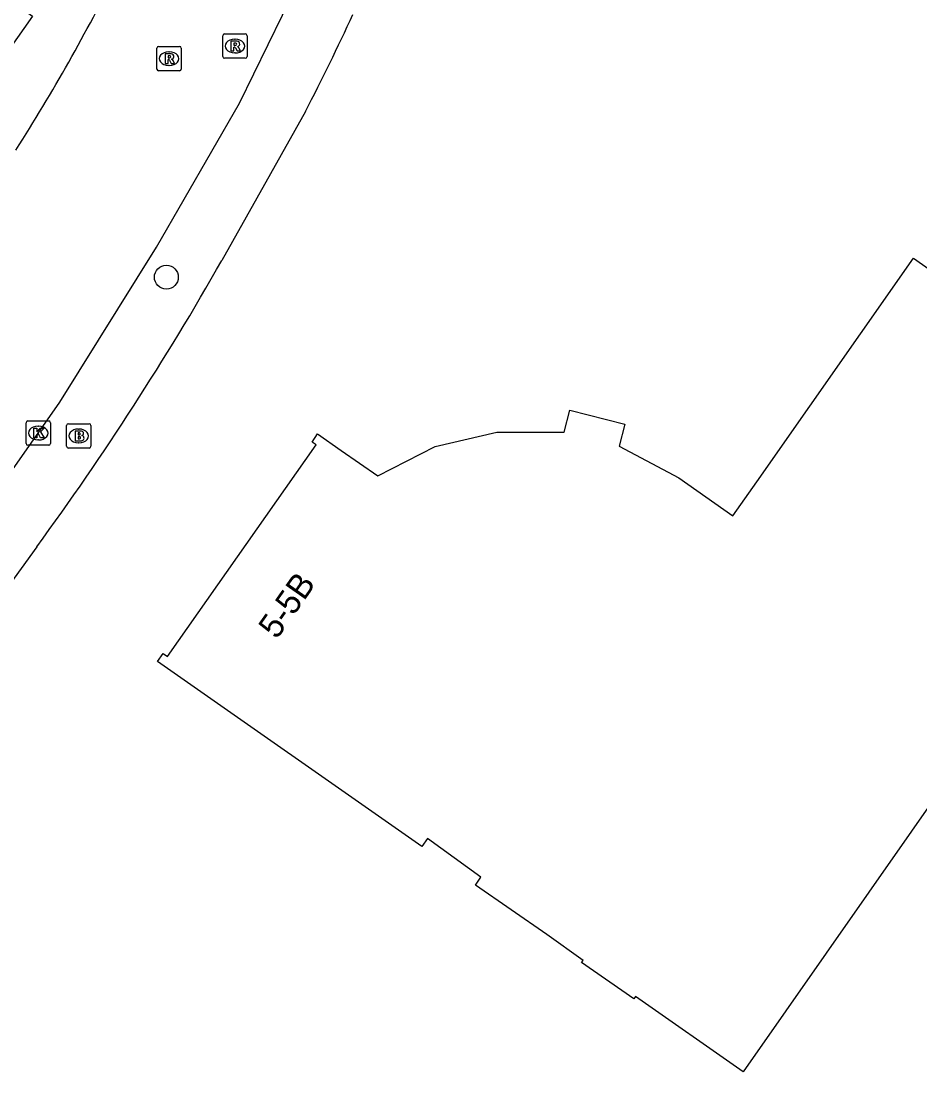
# Model space of a CAD drawing. Extents: x 155018 to 156648, y 383980 to 385733.
# Drawn here: x 155508.09 to 155544.91, y 385089.36 to 385132.44 of the extents above; entities that cross this region are included whole.
import ezdxf

# ---------------------------------------------------------------- set-up
doc = ezdxf.new("R2010")
doc.units = 0
for name, color, linetype in [('IMGEO_Boom', 7, 'Continuous'), ('IMGEO_Brandkraan', 7, 'Continuous'), ('IMGEO_Kolk', 7, 'Continuous'), ('IMGEO_Pand', 7, 'Continuous'), ('IMGEO_Pand_nummerreeks', 7, 'Continuous'), ('IMGEO_Rijbaan_lokaal_gesloten', 7, 'Continuous'), ('IMGEO_Rioolput', 7, 'Continuous'), ('IMGEO_Voetpad_open', 7, 'Continuous')]:
    doc.layers.add(name, color=color, linetype=linetype)

msp = doc.modelspace()

# ---------------------------------------------------------------- linework, layer by layer
at = {"layer": 'IMGEO_Boom'}
msp.add_circle((155514.041, 385121.939), 0.489, dxfattribs=at)
at = {"layer": 'IMGEO_Brandkraan'}
for p, q in [((155510.026, 385115.934), (155510.878, 385115.934)), ((155509.951, 385115.008), (155509.951, 385115.86)), ((155510.439, 385115.714), (155510.464, 385115.714)), ((155510.952, 385115.86), (155510.952, 385115.008)), ((155510.462, 385115.154), (155510.437, 385115.154)), ((155510.878, 385114.934), (155510.026, 385114.934))]:
    msp.add_line(p, q, dxfattribs=at)
for points in [[(155510.026, 385115.934), (155510.878, 385115.934)], [(155509.951, 385115.008), (155509.951, 385115.86)], [(155510.299, 385115.634), (155510.299, 385115.234), (155510.512, 385115.234)], [(155510.53, 385115.634), (155510.299, 385115.634)], [(155510.478, 385115.553), (155510.424, 385115.553), (155510.424, 385115.477)], [(155510.424, 385115.477), (155510.477, 385115.477)], [(155510.952, 385115.86), (155510.952, 385115.008)], [(155510.486, 385115.401), (155510.424, 385115.401), (155510.424, 385115.32)], [(155510.424, 385115.32), (155510.486, 385115.32)], [(155510.878, 385114.934), (155510.026, 385114.934)]]:
    msp.add_lwpolyline(points, dxfattribs=at)
for centre, radius, start, end in [((155510.028, 385115.858), 0.0765, 91.552, 178.448), ((155510.028, 385115.858), 0.0765, 91.552, 178.448), ((155510.876, 385115.858), 0.0765, 1.552, 88.448), ((155510.876, 385115.858), 0.0765, 1.552, 88.448), ((155510.479, 385115.515), 0.0379, 267.8285, 90.9355), ((155510.534, 385115.489), 0.145, 59.4692, 91.5367), ((155510.559, 385115.536), 0.0922, 285.5137, 58.1501), ((155510.564, 385115.344), 0.105, 301.3115, 78.989), ((155510.028, 385115.01), 0.0765, 181.552, 268.448), ((155510.028, 385115.01), 0.0765, 181.552, 268.448), ((155510.487, 385115.36), 0.0404, 269.8759, 90.5077), ((155510.518, 385115.485), 0.251, 268.6676, 293.5347), ((155510.876, 385115.01), 0.0765, 271.552, 358.448), ((155510.876, 385115.01), 0.0765, 271.552, 358.448)]:
    msp.add_arc(centre, radius, start, end, dxfattribs=at)
for centre, major_axis, ratio, start_param, end_param in [((155510.438, 385115.434), (-0.387, 0.002), 0.722429, 4.712389, 7.853982), ((155510.463, 385115.434), (-0.39, 0.002), 0.717154, 1.570796, 4.712389)]:
    msp.add_ellipse(centre, major_axis=major_axis, ratio=ratio, start_param=start_param, end_param=end_param, dxfattribs=at)
at = {"layer": 'IMGEO_Kolk'}
for p, q in [((155508.295, 385115.124), (155508.295, 385115.976)), ((155508.37, 385116.05), (155509.222, 385116.05)), ((155509.296, 385115.976), (155509.296, 385115.124)), ((155508.783, 385115.83), (155508.808, 385115.83)), ((155509.222, 385115.05), (155508.37, 385115.05)), ((155508.806, 385115.27), (155508.781, 385115.27))]:
    msp.add_line(p, q, dxfattribs=at)
for points in [[(155508.295, 385115.124), (155508.295, 385115.976)], [(155508.37, 385116.05), (155509.222, 385116.05)], [(155509.296, 385115.976), (155509.296, 385115.124)], [(155508.616, 385115.75), (155508.739, 385115.75), (155508.739, 385115.599), (155508.869, 385115.75), (155509.033, 385115.75), (155508.887, 385115.599), (155509.04, 385115.35), (155508.888, 385115.35), (155508.803, 385115.514), (155508.739, 385115.447), (155508.739, 385115.35), (155508.616, 385115.35), (155508.616, 385115.75)], [(155509.222, 385115.05), (155508.37, 385115.05)]]:
    msp.add_lwpolyline(points, dxfattribs=at)
for centre, start, end in [((155508.372, 385115.974), 91.552, 178.448), ((155508.372, 385115.974), 91.552, 178.448), ((155509.22, 385115.974), 1.552, 88.448), ((155509.22, 385115.974), 1.552, 88.448), ((155508.372, 385115.126), 181.552, 268.448), ((155508.372, 385115.126), 181.552, 268.448), ((155509.22, 385115.126), 271.552, 358.448), ((155509.22, 385115.126), 271.552, 358.448)]:
    msp.add_arc(centre, 0.0765, start, end, dxfattribs=at)
for centre, major_axis, ratio, start_param, end_param in [((155508.782, 385115.55), (-0.387, 0.002), 0.722429, 4.712389, 7.853982), ((155508.807, 385115.55), (-0.39, 0.002), 0.717154, 1.570796, 4.712389)]:
    msp.add_ellipse(centre, major_axis=major_axis, ratio=ratio, start_param=start_param, end_param=end_param, dxfattribs=at)
at = {"layer": 'IMGEO_Pand'}
for points in [[(155537.668, 385089.362), (155533.254, 385092.454), (155533.192, 385092.363), (155531.05, 385093.848), (155531.113, 385093.938), (155529.62, 385094.991), (155526.698, 385097.018), (155526.926, 385097.347), (155524.732, 385098.93), (155524.503, 385098.602), (155513.681, 385106.181), (155513.91, 385106.514), (155514.083, 385106.395), (155520.181, 385115.063), (155520.008, 385115.182), (155520.237, 385115.513), (155521.205, 385114.838), (155522.702, 385113.794), (155525.05, 385115.003), (155527.578, 385115.593), (155530.34, 385115.581), (155530.572, 385116.492), (155532.821, 385115.92), (155532.592, 385115.019), (155535.026, 385113.71), (155537.246, 385112.152), (155538.231, 385113.558), (155544.65, 385122.721), (155549.058, 385119.621)], [(155556.6, 385116.458), (155537.668, 385089.362)]]:
    msp.add_lwpolyline(points, dxfattribs=at)
at = {"layer": 'IMGEO_Rijbaan_lokaal_gesloten'}
msp.add_lwpolyline([(155504.455, 385109.355), (155509.68, 385116.82), (155513.64, 385123.17), (155517.035, 385129.07), (155519.387, 385133.898)], dxfattribs=at)
msp.add_arc((155441.608, 385169.351), 78.567, 327.50767, 333.64928, dxfattribs=at)
at = {"layer": 'IMGEO_Rioolput'}
for p, q in [((155516.349, 385130.986), (155516.349, 385131.838)), ((155516.424, 385131.912), (155517.276, 385131.912)), ((155517.35, 385131.838), (155517.35, 385130.986)), ((155513.726, 385131.398), (155514.578, 385131.398)), ((155516.837, 385131.692), (155516.862, 385131.692)), ((155513.651, 385130.472), (155513.651, 385131.324)), ((155514.139, 385131.178), (155514.164, 385131.178)), ((155514.652, 385131.324), (155514.652, 385130.472)), ((155516.86, 385131.132), (155516.835, 385131.132)), ((155514.162, 385130.618), (155514.137, 385130.618)), ((155517.276, 385130.912), (155516.424, 385130.912)), ((155514.578, 385130.398), (155513.726, 385130.398))]:
    msp.add_line(p, q, dxfattribs=at)
for points in [[(155516.349, 385130.986), (155516.349, 385131.838)], [(155516.424, 385131.912), (155517.276, 385131.912)], [(155517.35, 385131.838), (155517.35, 385130.986)], [(155513.726, 385131.398), (155514.578, 385131.398)], [(155516.938, 385131.61), (155516.686, 385131.612), (155516.686, 385131.212)], [(155516.686, 385131.212), (155516.81, 385131.212), (155516.81, 385131.374), (155516.821, 385131.374)], [(155516.864, 385131.531), (155516.81, 385131.531), (155516.81, 385131.45)], [(155516.81, 385131.45), (155516.862, 385131.45)], [(155513.651, 385130.472), (155513.651, 385131.324)], [(155514.24, 385131.096), (155513.988, 385131.098), (155513.988, 385130.698)], [(155514.166, 385131.017), (155514.112, 385131.017), (155514.112, 385130.936)], [(155514.652, 385131.324), (155514.652, 385130.472)], [(155516.868, 385131.345), (155516.939, 385131.212), (155517.079, 385131.212), (155517.014, 385131.338)], [(155513.988, 385130.698), (155514.112, 385130.698), (155514.112, 385130.86), (155514.123, 385130.86)], [(155514.112, 385130.936), (155514.164, 385130.936)], [(155514.17, 385130.831), (155514.241, 385130.698), (155514.381, 385130.698), (155514.316, 385130.824)], [(155517.276, 385130.912), (155516.424, 385130.912)], [(155514.578, 385130.398), (155513.726, 385130.398)]]:
    msp.add_lwpolyline(points, dxfattribs=at)
for centre, radius, start, end in [((155516.426, 385131.836), 0.0765, 91.552, 178.448), ((155516.426, 385131.836), 0.0765, 91.552, 178.448), ((155517.274, 385131.836), 0.0765, 1.552, 88.448), ((155517.274, 385131.836), 0.0765, 1.552, 88.448), ((155513.728, 385131.322), 0.0765, 91.552, 178.448), ((155513.728, 385131.322), 0.0765, 91.552, 178.448), ((155514.576, 385131.322), 0.0765, 1.552, 88.448), ((155514.576, 385131.322), 0.0765, 1.552, 88.448), ((155516.82, 385131.321), 0.0533, 26.0293, 88.6989), ((155516.846, 385131.639), 0.19, 274.7715, 282.9687), ((155516.87, 385131.435), 0.0964, 77.0061, 93.1865), ((155516.884, 385131.492), 0.0378, 276.6634, 79.6772), ((155516.937, 385131.5), 0.109, 350.3612, 89.416), ((155516.935, 385131.5), 0.112, 277.5842, 350.9817), ((155516.919, 385131.285), 0.108, 29.5134, 73.7905), ((155514.172, 385130.921), 0.0964, 77.0061, 93.1865), ((155514.186, 385130.978), 0.0378, 276.6634, 79.6772), ((155514.239, 385130.986), 0.109, 350.3612, 89.416), ((155514.237, 385130.986), 0.112, 277.5842, 350.9817), ((155516.426, 385130.988), 0.0765, 181.552, 268.448), ((155516.426, 385130.988), 0.0765, 181.552, 268.448), ((155517.274, 385130.988), 0.0765, 271.552, 358.448), ((155517.274, 385130.988), 0.0765, 271.552, 358.448), ((155514.122, 385130.807), 0.0533, 26.0293, 88.6989), ((155514.148, 385131.125), 0.19, 274.7715, 282.9687), ((155514.221, 385130.771), 0.108, 29.5134, 73.7905), ((155513.728, 385130.474), 0.0765, 181.552, 268.448), ((155513.728, 385130.474), 0.0765, 181.552, 268.448), ((155514.576, 385130.474), 0.0765, 271.552, 358.448), ((155514.576, 385130.474), 0.0765, 271.552, 358.448)]:
    msp.add_arc(centre, radius, start, end, dxfattribs=at)
for centre, major_axis, ratio, start_param, end_param in [((155516.836, 385131.412), (-0.387, 0.002), 0.722429, 4.712389, 7.853982), ((155516.861, 385131.412), (-0.39, 0.002), 0.717154, 1.570796, 4.712389), ((155514.138, 385130.898), (-0.387, 0.002), 0.722429, 4.712389, 7.853982), ((155514.163, 385130.898), (-0.39, 0.002), 0.717154, 1.570796, 4.712389)]:
    msp.add_ellipse(centre, major_axis=major_axis, ratio=ratio, start_param=start_param, end_param=end_param, dxfattribs=at)
at = {"layer": 'IMGEO_Voetpad_open'}
for points in [[(155512.006, 385141.006), (155510.941, 385137.798), (155510.234, 385136.1), (155510.135, 385136.111), (155507.992, 385133.028), (155508.553, 385132.633), (155500.688, 385121.46), (155500.792, 385121.366), (155500, 385120.251), (155495.738, 385114.252)], [(155519.739, 385128.737), (155516.317, 385122.629)], [(155508.732, 385110.886), (155506.969, 385108.464), (155507.669, 385107.967), (155507.272, 385107.392)]]:
    msp.add_lwpolyline(points, dxfattribs=at)
for centre, radius, start, end in [((155437.432, 385171.441), 92.726, 332.57789, 335.3115), ((155409.786, 385183.118), 122.507, 323.87002, 330.41179)]:
    msp.add_arc(centre, radius, start, end, dxfattribs=at)

# ---------------------------------------------------------------- texts
at = {"layer": 'IMGEO_Pand_nummerreeks'}
msp.add_text('5-5B', height=1, rotation=54.8733, dxfattribs=at).set_placement((155518.563, 385107.063))

doc.saveas('drawing.dxf')
